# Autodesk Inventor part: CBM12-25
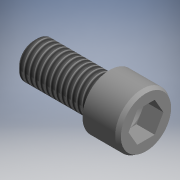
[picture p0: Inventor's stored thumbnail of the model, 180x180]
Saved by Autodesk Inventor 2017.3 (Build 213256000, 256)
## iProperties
Part Number: CBM12-25
Material: Generic
Catalog Web Link: www.cadenas.de
Description: CBM-Hex Socket Head Cap Screws - Bright Chromate Plating
Vendor: MISUMI
Document SubType Name: Modeling
Designer: partserver
Manufacturer: MISUMI
Mass: 5.24552 g
Surface Area: 22.8505 cm^2
Volume: 5.24552 cm^3
Density: 1 g/cm^3
Appearance: PSOLRGB-175-175-175
Category: PARTsolutions
Company: MISUMI
Title: CBM12-25
Author: Cadenas PARTsolutions
Comments: Hex Socket Head Cap Screws - Bright Chromate Plating
PSOL_IDENT_0: {$CADENAS_DATA\23d-libs\misumi\metric\27_screws_nuts\cbm.prj},155 {VTYP=3D},{NB=CBM12-25},{LINA=CBM1
PSOL_IDENT_1: 2-25},{NN=CBM},{DATE=07.06.2021 12:24:55},{GEOMDATE=24.03.2015 11:44:00},{VERSION=},{LINEID=50},{WBV
PSOL_IDENT_2: AR=L},{WBNUMERIC=L}  {NB=CBM12-25},{LINA=CBM12-25},{KT=DUMMY},{PN=CBM12-25},{TYPE=CBM},{M=12},{M1=12
PSOL_IDENT_3: },{L=25},{LALG=15,20,25,30,35,40,45,50,55,60},{LL=Studs - Fully Threaded},{A=18.0},{E=12},{B=10.0},{
PSOL_IDENT_4: LL3D=24.4},{TT3D=6},{R3D=0.600},{C3D=1.2},{A3D=-60}
NB: CBM12-25
NN: CBM
NT: Hex Socket Head Cap Screws - Bright Chromate Plating
NBSYN: $PN.
LINA: CBM12-25
CATALOG: Misumi
PN: CBM12-25
M: 12
L: 25
LL: Studs - Fully Threaded
A: 18
E: 12
B: 10
SUPPLIER: MISUMI
ARTICLENO: CBM12-25
BOMINFO: CBM12-25
CREATOR: CADENAS GmbH
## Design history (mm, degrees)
sketch "Sketch_8"
  geometry: L1 (25, 0)-(-12, 0); L2 (-12, 0)-(-12, 8.307); L3 (-12, 8.307)-(-10.8, 9); L4 (-10.8, 9)-(0, 9); L5 (0, 9)-(0, 6.6); L6 (0.6, 6)-(23.927, 6); L7 (23.927, 6)-(25, 4.927); L8 (25, 4.927)-(25, 0); L9 (25, 0)-(-12, 0); A1 r 0.6 centre (0.6, 6.6) between (0, 6.6) and (0.6, 6)
  constraints: 18 end point, 2 point on circle, 1 centre point
revolve "Revolution1" sketch "Sketch_8" stored, may be unused: angle "d0" = 360 deg
thread "Thread1" dims "d1" = 23.3265, "d2" = 0
sketch "Sketch2"
  geometry: 1 further point
hole "Hole1" sketch "Sketch2" at (0, 0) diameter "d3" = 10; stored, may be unused: countersink angle "d7" = 90 deg, drill point angle "d9" = 120 deg; dims "d4" = 6, "d5" = 4, "d6" = 2, "d8" = 6
sketch "Sketch_3"
  geometry: L1 (-5, -2.887)-(0, -5.774); L2 (0, -5.774)-(5, -2.887); L3 (5, -2.887)-(5, 2.887); L4 (5, 2.887)-(0, 5.774); L5 (0, 5.774)-(-5, 2.887); L6 (-5, 2.887)-(-5, -2.887)
  constraints: 12 end point
extrude "Extrusion1" cut sketch "Sketch_3" distance "d10" = 6; taper "d11" = 0 deg
node "bolt_XY"
node "bolt_YZ"
node "bolt_ZX"
node "bolt_X"
node "bolt_Y"
node "bolt_Z"
node "bolt_Center"
node "nut_XY"
node "nut_YZ"
node "nut_ZX"
node "nut_X"
node "nut_Y"
node "nut_Z"
node "nut_Center"
body "Solid1"
other parameters: "d12" = 0, "d13" = 0
